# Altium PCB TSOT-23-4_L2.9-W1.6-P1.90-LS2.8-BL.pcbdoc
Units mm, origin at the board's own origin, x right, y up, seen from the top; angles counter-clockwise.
Board outline 16.05 x 16.5 mm, 2 copper layers (Top Layer, Bottom Layer), stack 0 mm thick; 1 components, 0 nets, 4 pads, 0 vias.
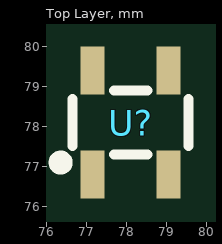
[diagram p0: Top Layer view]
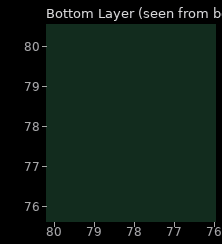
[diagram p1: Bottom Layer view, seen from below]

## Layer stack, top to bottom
Top Layer: signal copper (thickness not stored)
Bottom Layer: signal copper (thickness not stored)

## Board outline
85.9,69.85 69.85,69.85 69.85,86.35 85.9,86.35

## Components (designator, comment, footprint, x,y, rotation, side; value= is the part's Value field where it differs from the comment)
U? "" TSOT-23-4_L2.9-W1.6-P1.90-LS2.8-BL 78.1,78.1 r0 top

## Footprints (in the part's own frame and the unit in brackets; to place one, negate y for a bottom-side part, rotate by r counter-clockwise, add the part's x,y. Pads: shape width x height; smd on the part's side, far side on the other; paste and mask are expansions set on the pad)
TSOT-23-4_L2.9-W1.6-P1.90-LS2.8-BL [mm]
  rect 0.6x1.2 smd: 1(-0.95,-1.3) 2(0.95,-1.3) 3(0.95,1.3) 4(-0.95,1.3)
  silkscreen extent -1.9,-1.15 1.45,0.8

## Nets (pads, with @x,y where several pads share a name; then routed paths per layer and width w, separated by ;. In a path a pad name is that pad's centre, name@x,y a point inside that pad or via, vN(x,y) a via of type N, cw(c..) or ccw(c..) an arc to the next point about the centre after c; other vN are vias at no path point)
pads on no net: U?.1 U?.2 U?.3 U?.4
